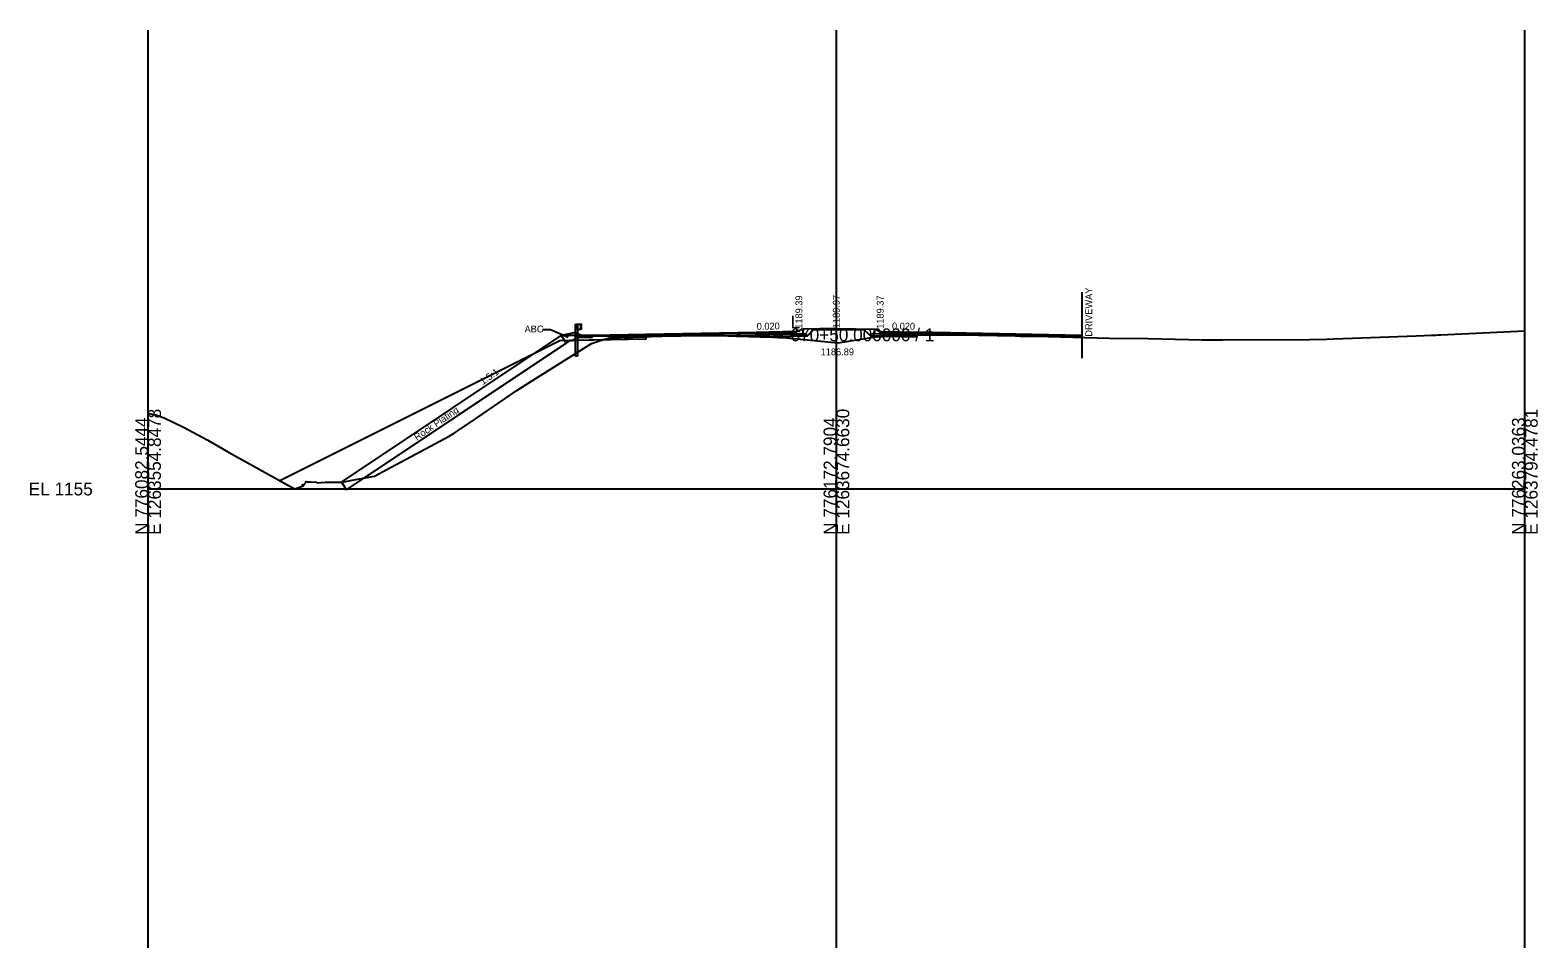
# Model space of a CAD drawing. Extents: x -41 to 1262860, y -100 to 777489.
# Drawn here: x -25.7 to 302.8, y 3610 to 3810 of the extents above; entities that cross this region are included whole.
import ezdxf

# ---------------------------------------------------------------- set-up
doc = ezdxf.new("R2010")
doc.units = 0
for name, color, linetype in [('Exist Cross Section Cell', 7, 'Continuous'), ('Exist XS Center Line Elevation Label', 7, 'Continuous'), ('Exist XS Ground Line', 7, 'Continuous'), ('Prop CMT Guardrail Graphics', 7, 'Continuous'), ('Prop CMT Pvmt Course 1', 7, 'Continuous'), ('Prop CMT Pvmt Course 4', 7, 'Continuous'), ('Prop CMT Pvmt Surface', 7, 'Continuous'), ('Prop CMT Shear Line', 7, 'Continuous'), ('Prop CMT Shld Paved Course 1', 7, 'Continuous'), ('Prop CMT Shld Paved Course 2', 7, 'Continuous'), ('Prop CMT Shld Paved Course 4', 7, 'Continuous'), ('Prop CMT Slope Grass', 7, 'Continuous'), ('Prop CMT Subgrade Earthwork', 7, 'Continuous'), ('Prop Conc Curb and Gutter', 7, 'Continuous'), ('Prop Conc Island Cover', 7, 'Continuous'), ('Prop XS Class II Rip Rap Ditch Liner', 7, 'Continuous'), ('Prop XS Earthwork Shape', 7, 'Continuous'), ('Prop XS Elevation Labels', 7, 'Continuous'), ('Prop XS Exc Vertical Line 1', 7, 'Continuous'), ('Prop XS Exc Vertical Line 2', 7, 'Continuous'), ('Prop XS Exc Vertical Line 3', 7, 'Continuous'), ('Prop XS Finish Grade', 7, 'Continuous'), ('Prop XS Hydro Elevations', 7, 'Continuous'), ('Prop XS SE Text', 7, 'Continuous'), ('Prop XS Side Slope Text', 7, 'Continuous'), ('Scratch_Level_0', 7, 'Continuous'), ('Scratch_Level_4', 7, 'Continuous'), ('Scratch_Level_6', 7, 'Continuous'), ('Typical Curb CELL', 7, 'Continuous')]:
    doc.layers.add(name, color=color, linetype=linetype)

msp = doc.modelspace()

# ---------------------------------------------------------------- linework, layer by layer
at = {"layer": 'Exist Cross Section Cell'}
for p, q in [((150, 3710), (150, 3745)), ((0, 3710), (150, 3710)), ((150, 3710), (300, 3710))]:
    msp.add_line(p, q, dxfattribs=at)
at = {"layer": 'Exist XS Ground Line'}
msp.add_lwpolyline([(0, 3726.43), (1.48, 3726.24), (3.53, 3725.5), (7.7, 3723.51), (12.99, 3720.64), (17.52, 3718.03), (30.27, 3710.96), (31.95, 3710.01), (33, 3710.43), (33.62, 3710.62), (33.66, 3711.01), (33.71, 3710.65), (34.38, 3711.5), (34.41, 3711.6), (34.65, 3711.59), (35.36, 3711.56), (36.66, 3711.46), (36.88, 3711.33), (38.57, 3711.51), (42.4, 3711.5), (44.47, 3711.89), (49.31, 3712.78), (52.01, 3714.26), (65.63, 3721.52), (66.73, 3722.18), (67.54, 3722.73), (71.36, 3725.3), (80.36, 3731.49), (82.99, 3733.16), (88.06, 3736.32), (96.61, 3741.71), (98.39, 3742.3), (100.54, 3742.96), (105.71, 3743.11), (108.16, 3743.17), (109.55, 3743.23), (111.92, 3743.32), (120.25, 3743.42), (124.39, 3743.47), (128.22, 3743.34), (136.25, 3743.08), (137.3, 3743.04), (139.11, 3742.95), (150.41, 3741.85), (150.41, 3741.85), (157.55, 3743.01), (158.55, 3743.16), (158.75, 3743.18), (161.24, 3743.33), (161.64, 3743.35), (165.16, 3743.51), (166.2, 3743.52), (176.93, 3743.63), (188.99, 3743.38), (189.51, 3743.37), (190, 3743.34), (190.23, 3743.33), (190.62, 3743.33), (196.15, 3743.22), (209.53, 3742.9), (217.92, 3742.81), (229.68, 3742.49), (230.34, 3742.49), (234.22, 3742.53), (253.11, 3742.61), (256.87, 3742.65), (258.45, 3742.73), (276.36, 3743.39), (278.09, 3743.46), (279.59, 3743.53), (280.59, 3743.54), (281.14, 3743.57), (281.68, 3743.62), (300, 3744.47)], dxfattribs=at)
at = {"layer": 'Prop CMT Guardrail Graphics'}
for p, q in [((93.11, 3745.95), (93.59, 3745.95)), ((93.11, 3743.45), (93.11, 3745.95)), ((93.59, 3744.76), (93.59, 3745.95)), ((93.59, 3745.95), (94.26, 3745.95)), ((93.59, 3745.95), (93.59, 3743.44)), ((94.26, 3745.95), (94.26, 3744.76)), ((94.26, 3745.87), (94.26, 3744.84)), ((94.36, 3745.85), (94.26, 3745.87)), ((94.27, 3745.4), (94.5, 3745.6)), ((94.27, 3745.31), (94.27, 3745.4)), ((94.5, 3745.11), (94.27, 3745.31)), ((94.5, 3745.75), (94.36, 3745.85)), ((94.5, 3745.6), (94.5, 3745.75)), ((93.11, 3738.95), (93.11, 3743.45)), ((94.26, 3744.76), (93.59, 3744.76)), ((93.59, 3743.44), (93.59, 3738.95)), ((94.26, 3744.84), (94.36, 3744.87)), ((94.36, 3744.87), (94.5, 3744.97)), ((94.5, 3744.97), (94.5, 3745.11)), ((93.59, 3738.95), (93.11, 3738.95))]:
    msp.add_line(p, q, dxfattribs=at)
at = {"layer": 'Prop CMT Pvmt Course 1'}
for p, q in [((132.5, 3744.2), (141.22, 3744.37)), ((132.5, 3743.95), (141.22, 3744.12)), ((141.22, 3744.12), (141.22, 3744.37)), ((159.84, 3744.35), (159.84, 3744.1)), ((159.84, 3744.1), (167.5, 3743.95))]:
    msp.add_line(p, q, dxfattribs=at)
for points in [[(108.5, 3743.47), (108.5, 3743.72), (108.5, 3743.72), (132.5, 3744.2), (132.5, 3743.95), (132.5, 3743.95), (108.5, 3743.47), (108.5, 3743.47), (108.5, 3743.47)], [(203.5, 3743.23), (203.5, 3743.48), (203.5, 3743.48), (167.5, 3744.2), (167.5, 3743.95), (167.5, 3743.95), (203.5, 3743.23), (203.5, 3743.23), (203.5, 3743.23)]]:
    msp.add_lwpolyline(points, dxfattribs=at)
at = {"layer": 'Prop CMT Pvmt Course 4'}
msp.add_line((108.5, 3742.68), (93.44, 3742.38), dxfattribs=at)
at = {"layer": 'Prop CMT Pvmt Surface'}
for p, q in [((96.84, 3743.49), (108.5, 3743.72)), ((108.5, 3743.72), (132.5, 3744.2)), ((132.5, 3744.2), (141.22, 3744.37)), ((159.84, 3744.35), (167.5, 3744.2)), ((167.5, 3744.2), (203.5, 3743.48))]:
    msp.add_line(p, q, dxfattribs=at)
at = {"layer": 'Prop CMT Shear Line'}
msp.add_line((203.5, 3752.92), (203.5, 3738.48), dxfattribs=at)
at = {"layer": 'Prop CMT Shld Paved Course 1'}
for p, q in [((108.5, 3743.47), (96.85, 3743.24)), ((104.5, 3743.64), (104.5, 3743.64)), ((108.5, 3743.72), (108.5, 3743.47)), ((108.5, 3743.47), (108.5, 3743.47))]:
    msp.add_line(p, q, dxfattribs=at)
at = {"layer": 'Prop CMT Shld Paved Course 2'}
for p, q in [((108.5, 3743.14), (100.54, 3742.98)), ((103.9, 3743.04), (103.9, 3743.04)), ((103.9, 3743.04), (103.9, 3743.04)), ((103.9, 3743.04), (103.9, 3743.04)), ((103.9, 3743.04), (103.9, 3743.04)), ((109.55, 3743.49), (108.5, 3743.47)), ((108.5, 3743.47), (108.5, 3743.14)), ((108.5, 3743.47), (108.5, 3743.19)), ((108.5, 3743.19), (109.55, 3743.23)), ((108.5, 3743.19), (108.5, 3743.19)), ((108.5, 3743.14), (108.5, 3743.14)), ((111.92, 3743.54), (109.55, 3743.49)), ((109.55, 3743.49), (109.55, 3743.49)), ((109.55, 3743.23), (111.92, 3743.32)), ((109.55, 3743.23), (109.55, 3743.23)), ((120.25, 3743.7), (111.92, 3743.54)), ((111.92, 3743.54), (111.92, 3743.54)), ((111.92, 3743.54), (111.92, 3743.54)), ((111.92, 3743.32), (120.25, 3743.42)), ((111.92, 3743.32), (111.92, 3743.32)), ((111.92, 3743.32), (111.92, 3743.32)), ((124.39, 3743.79), (120.25, 3743.7)), ((120.25, 3743.7), (120.25, 3743.7)), ((120.25, 3743.42), (124.39, 3743.47)), ((120.25, 3743.42), (120.25, 3743.42)), ((128.22, 3743.86), (124.39, 3743.79)), ((124.39, 3743.47), (124.39, 3743.47)), ((124.39, 3743.47), (124.65, 3743.46)), ((124.65, 3743.46), (128.22, 3743.53)), ((132.5, 3743.95), (128.22, 3743.86)), ((128.22, 3743.86), (128.22, 3743.86)), ((128.22, 3743.53), (132.5, 3743.62)), ((128.22, 3743.53), (128.22, 3743.53)), ((132.5, 3743.62), (132.5, 3743.95)), ((132.5, 3743.62), (141.22, 3743.79)), ((132.5, 3743.62), (132.5, 3743.62)), ((141.22, 3744.12), (141.22, 3743.79)), ((159.84, 3743.77), (159.84, 3744.1)), ((159.84, 3743.77), (167.5, 3743.62)), ((167.5, 3743.62), (167.5, 3743.95)), ((167.5, 3743.95), (167.5, 3743.95)), ((167.5, 3743.95), (176.93, 3743.76)), ((170.16, 3743.56), (167.5, 3743.62)), ((167.5, 3743.62), (167.5, 3743.62)), ((167.5, 3743.62), (167.5, 3743.62)), ((176.93, 3743.63), (170.16, 3743.56)), ((170.16, 3743.56), (170.16, 3743.56)), ((176.93, 3743.76), (176.93, 3743.76)), ((176.93, 3743.76), (176.93, 3743.76)), ((176.93, 3743.76), (188.99, 3743.52)), ((188.99, 3743.38), (176.93, 3743.63)), ((176.93, 3743.63), (176.93, 3743.63)), ((176.93, 3743.63), (176.93, 3743.63)), ((188.99, 3743.52), (188.99, 3743.52)), ((188.99, 3743.52), (189.51, 3743.51)), ((189.51, 3743.37), (188.99, 3743.38)), ((188.99, 3743.38), (188.99, 3743.38)), ((189.51, 3743.51), (190, 3743.5)), ((190, 3743.34), (189.51, 3743.37)), ((190, 3743.5), (190.23, 3743.49)), ((190.23, 3743.33), (190, 3743.34)), ((190.23, 3743.49), (190.62, 3743.49)), ((190.62, 3743.33), (190.23, 3743.33)), ((190.62, 3743.49), (190.62, 3743.49)), ((190.62, 3743.49), (196.15, 3743.38)), ((196.15, 3743.22), (190.62, 3743.33)), ((190.62, 3743.33), (190.62, 3743.33)), ((196.15, 3743.38), (196.15, 3743.38)), ((196.15, 3743.38), (196.15, 3743.38)), ((196.15, 3743.38), (203.5, 3743.23)), ((203.5, 3743.04), (196.15, 3743.22)), ((196.15, 3743.22), (196.15, 3743.22)), ((196.15, 3743.22), (196.15, 3743.22)), ((196.15, 3743.22), (196.15, 3743.22)), ((203.5, 3743.23), (203.5, 3743.23)), ((203.5, 3743.23), (203.5, 3743.04)), ((203.5, 3743.04), (203.5, 3743.04)), ((203.5, 3743.04), (203.5, 3743.04)), ((203.5, 3743.04), (203.5, 3743.04))]:
    msp.add_line(p, q, dxfattribs=at)
at = {"layer": 'Prop CMT Shld Paved Course 4'}
for p, q in [((92.58, 3742.36), (93.32, 3743.1)), ((92.58, 3742.36), (93.32, 3743.1)), ((93.32, 3743.1), (93.83, 3743.1)), ((93.32, 3743.1), (93.83, 3743.1)), ((103.9, 3743.04), (103.9, 3743.04)), ((103.9, 3743.04), (103.9, 3743.04)), ((108.5, 3743.14), (108.5, 3742.68)), ((128.22, 3743.34), (124.65, 3743.46)), ((128.22, 3743.34), (132.5, 3743.21)), ((132.5, 3743.16), (132.5, 3743.62)), ((132.5, 3743.16), (143.66, 3743.38)), ((141.22, 3743.79), (143.22, 3743.83)), ((143.22, 3743.83), (143.66, 3743.38)), ((157.84, 3743.81), (157.39, 3743.36)), ((157.39, 3743.36), (167.5, 3743.16)), ((159.84, 3743.77), (157.84, 3743.81)), ((167.5, 3743.16), (167.5, 3743.62)), ((170.16, 3743.56), (167.5, 3743.54))]:
    msp.add_line(p, q, dxfattribs=at)
at = {"layer": 'Prop CMT Slope Grass'}
for q in [(90, 3743.42), (93.83, 3743.78)]:
    msp.add_line((93.14, 3744.12), q, dxfattribs=at)
at = {"layer": 'Prop CMT Subgrade Earthwork'}
for p, q in [((108.5, 3742.68), (91.99, 3742.35)), ((108.5, 3742.68), (108.5, 3743.19)), ((143.66, 3743.38), (132.5, 3743.16)), ((132.5, 3743.16), (132.5, 3743.21)), ((143.66, 3743.38), (145.15, 3744.87)), ((157.39, 3743.36), (155.9, 3744.85)), ((157.39, 3743.36), (167.5, 3743.16)), ((167.5, 3743.16), (167.5, 3743.54))]:
    msp.add_line(p, q, dxfattribs=at)
at = {"layer": 'Prop Conc Curb and Gutter'}
for p, q in [((141.9, 3744.39), (141.22, 3744.37)), ((141.22, 3744.37), (141.22, 3743.79)), ((141.22, 3743.79), (142.72, 3743.82)), ((141.97, 3744.46), (141.97, 3744.45)), ((142.72, 3744.82), (142.07, 3744.6)), ((142.72, 3743.82), (142.72, 3744.82)), ((142.72, 3743.82), (142.72, 3743.82)), ((158.34, 3744.8), (158.99, 3744.58)), ((158.34, 3743.8), (158.34, 3744.8)), ((159.84, 3743.77), (158.34, 3743.8)), ((159.09, 3744.44), (159.09, 3744.43)), ((159.15, 3744.37), (159.84, 3744.35)), ((159.84, 3743.77), (159.84, 3744.35))]:
    msp.add_line(p, q, dxfattribs=at)
for centre, radius, start, end in [((141.9, 3744.45), 0.0625, 271.1458, 360), ((142.11, 3744.46), 0.146, 108.435, 180), ((158.94, 3744.44), 0.146, 0, 71.565), ((159.15, 3744.43), 0.0625, 180, 268.8542)]:
    msp.add_arc(centre, radius, start, end, dxfattribs=at)
at = {"layer": 'Prop Conc Island Cover'}
for p, q in [((150, 3744.97), (142.72, 3744.82)), ((142.72, 3744.55), (142.72, 3744.55)), ((150, 3744.97), (158.34, 3744.8))]:
    msp.add_line(p, q, dxfattribs=at)
at = {"layer": 'Prop XS Class II Rip Rap Ditch Liner'}
for p, q in [((42.12, 3711.5), (90, 3743.42)), ((43.23, 3709.84), (91.99, 3742.35)), ((85.96, 3744.79), (87.66, 3744.79)), ((87.66, 3744.79), (91.55, 3743.09)), ((93.83, 3743.42), (90, 3743.42)), ((90, 3743.42), (91.11, 3741.76)), ((91.11, 3741.76), (91.99, 3742.34)), ((91.99, 3742.34), (92.58, 3742.36)), ((92.58, 3742.36), (93.32, 3743.1)), ((93.32, 3743.1), (93.83, 3743.1)), ((93.83, 3743.1), (93.83, 3743.42)), ((42.12, 3711.5), (43.23, 3709.84))]:
    msp.add_line(p, q, dxfattribs=at)
at = {"layer": 'Prop XS Earthwork Shape'}
for points in [[(44.47, 3711.89), (49.31, 3712.78), (52.01, 3714.26), (65.63, 3721.52), (66.73, 3722.18), (67.54, 3722.73), (71.36, 3725.3), (80.36, 3731.49), (82.99, 3733.16), (88.06, 3736.32), (96.61, 3741.71), (98.39, 3742.3), (99, 3742.49), (93.44, 3742.38), (89.7, 3742.3), (28.73, 3711.81), (30.27, 3710.96), (31.95, 3710.01), (33, 3710.43), (33.62, 3710.62), (33.66, 3711.01), (33.71, 3710.65), (34.38, 3711.5), (34.41, 3711.6), (34.65, 3711.59), (35.36, 3711.56), (36.66, 3711.46), (36.88, 3711.33), (38.57, 3711.51), (42.4, 3711.5)], [(99, 3742.49), (100.54, 3742.96), (105.71, 3743.11), (108.16, 3743.17), (108.5, 3743.19), (108.5, 3742.68)], [(132.5, 3743.16), (132.5, 3743.21), (133.42, 3743.18)], [(143.66, 3743.38), (133.42, 3743.18), (136.25, 3743.08), (137.3, 3743.04), (139.11, 3742.95), (150.41, 3741.85), (157.55, 3743.01), (158.55, 3743.16), (158.75, 3743.18), (160.61, 3743.3), (157.39, 3743.36), (156.15, 3744.59), (150, 3744.72), (144.9, 3744.61)], [(167.5, 3743.16), (167.5, 3743.54), (166.2, 3743.52), (165.16, 3743.51), (161.64, 3743.35), (161.24, 3743.33), (160.61, 3743.3)]]:
    msp.add_lwpolyline(points, close=True, dxfattribs=at)
at = {"layer": 'Prop XS Exc Vertical Line 1'}
msp.add_line((0, 3610), (0, 3810), dxfattribs=at)
at = {"layer": 'Prop XS Exc Vertical Line 2'}
msp.add_line((150, 3610), (150, 3810), dxfattribs=at)
at = {"layer": 'Prop XS Exc Vertical Line 3'}
msp.add_line((300, 3610), (300, 3810), dxfattribs=at)
at = {"layer": 'Prop XS Finish Grade'}
msp.add_line((91.11, 3741.76), (47.01, 3712.36), dxfattribs=at)
at = {"layer": 'Scratch_Level_0'}
for p, q in [((142.72, 3744.82), (142.72, 3744.57)), ((158.34, 3744.8), (158.34, 3744.55))]:
    msp.add_line(p, q, dxfattribs=at)
at = {"layer": 'Scratch_Level_4'}
msp.add_line((300, 3610), (300, 3810), dxfattribs=at)
at = {"layer": 'Scratch_Level_6'}
msp.add_line((0, 3610), (0, 3810), dxfattribs=at)
at = {"layer": 'Typical Curb CELL'}
for p, q in [((93.83, 3743.1), (93.83, 3743.78)), ((94.52, 3743.43), (93.83, 3743.78)), ((93.83, 3743.1), (96.85, 3743.07)), ((93.87, 3743.4), (94.02, 3743.44)), ((94, 3743.35), (93.87, 3743.4)), ((94.02, 3743.44), (94, 3743.35)), ((94.54, 3743.31), (94.43, 3743.23)), ((94.43, 3743.23), (94.6, 3743.19)), ((96.84, 3743.49), (94.52, 3743.43)), ((94.6, 3743.19), (94.54, 3743.31)), ((95.28, 3743.36), (95.24, 3743.24)), ((95.24, 3743.24), (95.36, 3743.24)), ((95.36, 3743.24), (95.28, 3743.36)), ((95.78, 3743.3), (95.68, 3743.22)), ((95.68, 3743.22), (95.85, 3743.18)), ((95.85, 3743.18), (95.78, 3743.3)), ((96.53, 3743.34), (96.49, 3743.23)), ((96.49, 3743.23), (96.61, 3743.22)), ((96.61, 3743.22), (96.53, 3743.34)), ((96.85, 3743.49), (96.85, 3743.49)), ((96.85, 3743.07), (96.85, 3743.48))]:
    msp.add_line(p, q, dxfattribs=at)
for centre in [(93.9, 3743.48), (93.99, 3743.21), (94.11, 3743.26), (94.37, 3743.28), (94.38, 3743.23), (94.56, 3743.15), (94.59, 3743.25), (94.78, 3743.21), (94.83, 3743.32), (94.96, 3743.29), (94.99, 3743.17), (95.05, 3743.2), (95.24, 3743.2), (95.36, 3743.25), (95.45, 3743.24), (95.55, 3743.19), (95.61, 3743.33), (95.62, 3743.27), (95.63, 3743.22), (95.84, 3743.24), (96.03, 3743.19), (96.08, 3743.31), (96.13, 3743.28), (96.21, 3743.28), (96.24, 3743.15), (96.29, 3743.19), (96.36, 3743.36), (96.72, 3743.44), (96.76, 3743.31)]:
    msp.add_circle(centre, 0.00802, dxfattribs=at)
msp.add_arc((96.84, 3743.48), 0.0104, 359.4338, 91.4818, dxfattribs=at)

# ---------------------------------------------------------------- texts
at = {"layer": 'Exist Cross Section Cell'}
for s, p in [('L', (140, 3745)), ('670+50.000000 / 1', (140, 3742.2)), ('EL 1155', (-26, 3708.6))]:
    msp.add_text(s, height=2.8, dxfattribs=at).set_placement(p)
for s, p in [('E 1263554.8478', (2.8, 3700)), ('E 1263674.6630', (152.8, 3700)), ('E 1263794.4781', (302.8, 3700)), ('N 776082.5444', (0, 3700)), ('N 776172.7904', (150, 3700)), ('N 776263.0363', (300, 3700))]:
    msp.add_text(s, height=2.8, rotation=90, dxfattribs=at).set_placement(p)
at = {"layer": 'Exist XS Center Line Elevation Label'}
msp.add_text('1186.89', height=1.5, dxfattribs=at).set_placement((146.57, 3739.14))
at = {"layer": 'Prop XS Elevation Labels'}
for s, p in [('1189.39', (142.57, 3744.93)), ('1189.37', (160.28, 3744.92))]:
    msp.add_text(s, height=1.5, rotation=90, dxfattribs=at).set_placement(p)
at = {"layer": 'Prop XS Hydro Elevations'}
for s, p in [('1189.97', (150.72, 3745.06)), ('DRIVEWAY', (205.73, 3743.2))]:
    msp.add_text(s, height=1.5, rotation=90, dxfattribs=at).set_placement(p)
at = {"layer": 'Prop XS SE Text'}
for rotation, p in [(1.1458, (132.64, 3744.69)), (358.8542, (162.09, 3744.8))]:
    msp.add_text('0.020', height=1.5, rotation=rotation, dxfattribs=at).set_placement(p)
at = {"layer": 'Prop XS Side Slope Text'}
for s, rotation, p in [('ABC', 0.2627, (82.05, 3744.11)), ('1.5:1', 35.2045, (72.96, 3732.61)), ('Rock Plating', 34.4049, (58.6, 3720.49))]:
    msp.add_text(s, height=1.5, rotation=rotation, dxfattribs=at).set_placement(p)

doc.saveas('drawing.dxf')
